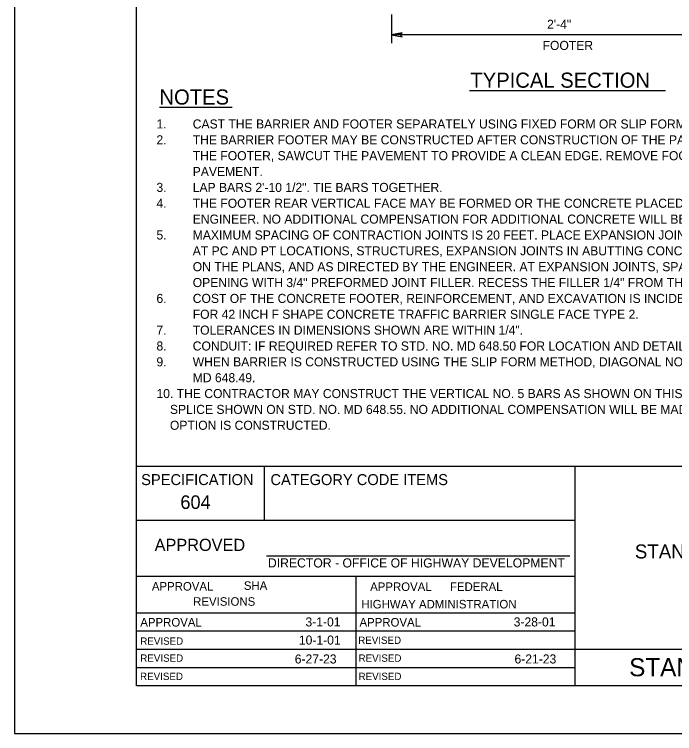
# Model space of a CAD drawing. Extents: x -27.4 to -18.9, y -4.2 to 6.8.
# Drawn here: x -27.416 to -23.046, y -4.191 to 0.571 of the extents above; entities that cross this region are included whole.
import ezdxf

# ---------------------------------------------------------------- set-up
doc = ezdxf.new("R2010")
doc.units = 0
for name, color, linetype in [('BORD-LINE', 7, 'Continuous'), ('DETL-DIMS', 7, 'Continuous'), ('Level 10', 7, 'Continuous'), ('Level 12', 7, 'Continuous'), ('Level 13', 7, 'Continuous'), ('TTLB-TEXT', 7, 'Continuous'), ('USER-CLIP', 7, 'Continuous')]:
    doc.layers.add(name, color=color, linetype=linetype)

msp = doc.modelspace()

# ---------------------------------------------------------------- linework, layer by layer
at = {"layer": 'BORD-LINE'}
for p, q in [((-23.7053, -2.4232), (-26.6066, -2.4232)), ((-25.7604, -2.7779), (-25.7604, -2.4232)), ((-23.7053, -3.874), (-23.7053, -2.4232)), ((-19.2324, -2.4232), (-23.7053, -2.4232)), ((-26.6066, -2.7779), (-23.7053, -2.7779)), ((-25.7474, -3.013), (-23.7405, -3.013)), ((-26.6066, -3.1486), (-25.7604, -3.1486)), ((-26.6066, -3.874), (-26.6066, -3.1486)), ((-26.6066, -3.1486), (-23.7053, -3.1486)), ((-25.156, -3.1486), (-25.156, -3.874)), ((-26.6066, -3.3904), (-23.7053, -3.3904)), ((-26.6066, -3.5113), (-23.7053, -3.5113)), ((-26.6066, -3.6322), (-23.7053, -3.6322)), ((-23.7053, -3.6322), (-19.2324, -3.6322)), ((-26.6066, -3.7531), (-23.7053, -3.7531)), ((-25.7604, -3.7531), (-23.7053, -3.7531))]:
    msp.add_line(p, q, dxfattribs=at)
msp.add_lwpolyline([(-26.6066, 6.4791), (-19.2324, 6.4791), (-19.2324, -3.874), (-26.6066, -3.874)], close=True, dxfattribs=at)
at = {"layer": 'DETL-DIMS'}
for p, q in [((-24.9207, 0.4358), (-24.8492, 0.4484)), ((-24.9207, 0.4358), (-24.8492, 0.4232)), ((-24.8492, 0.4484), (-24.8627, 0.4358)), ((-24.8627, 0.4358), (-24.8492, 0.4232))]:
    msp.add_line(p, q, dxfattribs=at)
msp.add_lwpolyline([(-24.8492, 0.4484), (-24.9207, 0.4358), (-24.8492, 0.4232), (-24.8627, 0.4358)], close=True, dxfattribs=at)
at = {"layer": 'Level 10'}
for p, q in [((-24.9207, 0.5695), (-24.9207, 0.3817)), ((-22.588, 0.4358), (-24.9207, 0.4358))]:
    msp.add_line(p, q, dxfattribs=at)
at = {"layer": 'Level 12'}
msp.add_line((-24.4033, 0.067), (-23.1064, 0.067), dxfattribs=at)
at = {"layer": 'Level 13'}
msp.add_line((-26.4557, -0.0429), (-25.9753, -0.0429), dxfattribs=at)
at = {"layer": 'USER-CLIP'}
msp.add_lwpolyline([(-18.9155, 6.8091), (-27.4155, 6.8091), (-27.4155, -4.1909), (-18.9155, -4.1909)], close=True, dxfattribs=at)

# ---------------------------------------------------------------- texts
at = {"layer": 'Level 12'}
for s, height, p in [('2\'-4"', 0.06001, (-23.8905, 0.4758)), ('FOOTER', 0.06001, (-23.9201, 0.3358)), ('TYPICAL SECTION', 0.1, (-24.398, 0.0857))]:
    msp.add_text(s, height=height, dxfattribs=at).set_placement(p)
at = {"layer": 'Level 13'}
for s, height, p in [('NOTES', 0.1, (-26.4556, -0.0258)), ('1.', 0.06, (-26.4754, -0.1843)), ('CAST THE BARRIER AND FOOTER SEPARATELY USING FIXED FORM OR SLIP FORM CONSTRUCTION WITH CONCRETE MIX NO.6 (4500 PSI).', 0.06, (-26.2354, -0.1843)), ('2.', 0.06, (-26.4754, -0.2893)), ('THE BARRIER FOOTER MAY BE CONSTRUCTED AFTER CONSTRUCTION OF THE PAVEMENT. IF FLEXIBLE PAVEMENT IS CONSTRUCTED BEFORE ', 0.06, (-26.2354, -0.2893)), ('THE FOOTER, SAWCUT THE PAVEMENT TO PROVIDE A CLEAN EDGE. REMOVE FOOTER FORMS IF THE FOOTER IS CONSTRUCTED BEFORE THE', 0.06, (-26.2354, -0.3943)), ('PAVEMENT.', 0.06, (-26.2354, -0.4993)), ('3.', 0.06, (-26.4754, -0.6043)), ('LAP BARS 2\'-10 1/2". TIE BARS TOGETHER.', 0.06, (-26.2354, -0.6043)), ('4.', 0.06, (-26.4754, -0.7093)), ('THE FOOTER REAR VERTICAL FACE MAY BE FORMED OR THE CONCRETE PLACED AGAINST THE VERTICAL EARTH SIDE IF APPROVED BY THE ', 0.06, (-26.2354, -0.7093)), ('ENGINEER. NO ADDITIONAL COMPENSATION FOR ADDITIONAL CONCRETE WILL BE PAID IF CONCRETE IS PLACED AGAINST THE EARTH. ', 0.06, (-26.2354, -0.8143)), ('5.', 0.06, (-26.4754, -0.9193)), ('MAXIMUM SPACING OF CONTRACTION JOINTS IS 20 FEET. PLACE EXPANSION JOINTS IN THE BARRIER AND FOOTER AT THE END OF POUR.', 0.06, (-26.2354, -0.9193)), ('AT PC AND PT LOCATIONS, STRUCTURES, EXPANSION JOINTS IN ABUTTING CONCRETE AND UNDERLYING CONCRETE. LOCATIONS AS SHOWN', 0.06, (-26.2354, -1.0243)), ('ON THE PLANS, AND AS DIRECTED BY THE ENGINEER. AT EXPANSION JOINTS, SPACE BARRIER SECTIONS 3/4" APART AND FILL THE ', 0.06, (-26.2354, -1.1293)), ('OPENING WITH 3/4" PREFORMED JOINT FILLER. RECESS THE FILLER 1/4" FROM THE FACE OF BARRIER.', 0.06, (-26.2354, -1.2343)), ('6.', 0.06, (-26.4754, -1.3393)), ('COST OF THE CONCRETE FOOTER, REINFORCEMENT, AND EXCAVATION IS INCIDENTAL TO THE CONTRACT UNIT PRICE PER LINEAR FOOT ', 0.06, (-26.2354, -1.3393)), ('FOR 42 INCH F SHAPE CONCRETE TRAFFIC BARRIER SINGLE FACE TYPE 2.', 0.06, (-26.2354, -1.4443)), ('7.', 0.06, (-26.4754, -1.5493)), ('TOLERANCES IN DIMENSIONS SHOWN ARE WITHIN 1/4".', 0.06, (-26.2354, -1.5493)), ('8.', 0.06, (-26.4754, -1.6543)), ('CONDUIT: IF REQUIRED REFER TO STD. NO. MD 648.50 FOR LOCATION AND DETAILS.', 0.06, (-26.2354, -1.6543)), ('9.', 0.06, (-26.4754, -1.7593)), ('WHEN BARRIER IS CONSTRUCTED USING THE SLIP FORM METHOD, DIAGONAL NO.4 BARS ARE REQUIRED, SEE STD. NO. ', 0.06, (-26.2354, -1.7593)), ('MD 648.49.', 0.06, (-26.2354, -1.8643)), ('10. THE CONTRACTOR MAY CONSTRUCT THE VERTICAL NO. 5 BARS AS SHOWN ON THIS STANDARD OR USE THE LAP', 0.06, (-26.4754, -1.9693)), ('    SPLICE SHOWN ON STD. NO. MD 648.55. NO ADDITIONAL COMPENSATION WILL BE MADE FOR WHICHEVER', 0.06, (-26.4754, -2.0743)), ('    OPTION IS CONSTRUCTED.', 0.06, (-26.4754, -2.1793)), ('604', 0.09001, (-26.3173, -2.7033)), ('3-1-01', 0.06, (-25.4893, -3.4813)), ('3-28-01', 0.06, (-24.1113, -3.4813)), ('10-1-01', 0.06, (-25.5329, -3.6013)), ('6-27-23', 0.06, (-25.5602, -3.7266)), ('6-21-23', 0.06, (-24.106, -3.7266))]:
    msp.add_text(s, height=height, dxfattribs=at).set_placement(p)
at = {"layer": 'TTLB-TEXT'}
for s, height, p in [('SPECIFICATION', 0.07254, (-26.5765, -2.5453)), ('CATEGORY CODE ITEMS ', 0.07254, (-25.7211, -2.5453)), ('APPROVED', 0.0806, (-26.4874, -2.9816)), ('STANDARDS FOR HIGHWAYS AND INCIDENTAL STRUCTURES', 0.09269, (-23.3095, -3.0312)), ('DIRECTOR - OFFICE OF HIGHWAY DEVELOPMENT', 0.0604, (-25.7379, -3.0908)), ('APPROVAL', 0.05642, (-26.5056, -3.2438)), ('SHA', 0.05642, (-25.897, -3.2391)), ('APPROVAL', 0.05642, (-25.0611, -3.2463)), ('FEDERAL', 0.05642, (-24.533, -3.2462)), ('REVISIONS', 0.05642, (-26.2325, -3.3443)), ('HIGHWAY ADMINISTRATION', 0.05642, (-25.1196, -3.362)), ('APPROVAL', 0.05642, (-26.5822, -3.482)), ('APPROVAL', 0.05642, (-25.1316, -3.482)), ('REVISED', 0.04836, (-26.5825, -3.6025)), ('REVISED', 0.04836, (-25.1403, -3.5966)), ('REVISED', 0.04836, (-26.5825, -3.7151)), ('REVISED', 0.04836, (-25.138, -3.7151)), ('STANDARD NO.', 0.12, (-23.3471, -3.8111)), ('REVISED', 0.04836, (-26.5838, -3.8359)), ('REVISED', 0.04836, (-25.138, -3.8359))]:
    msp.add_text(s, height=height, dxfattribs=at).set_placement(p)

doc.saveas('drawing.dxf')
